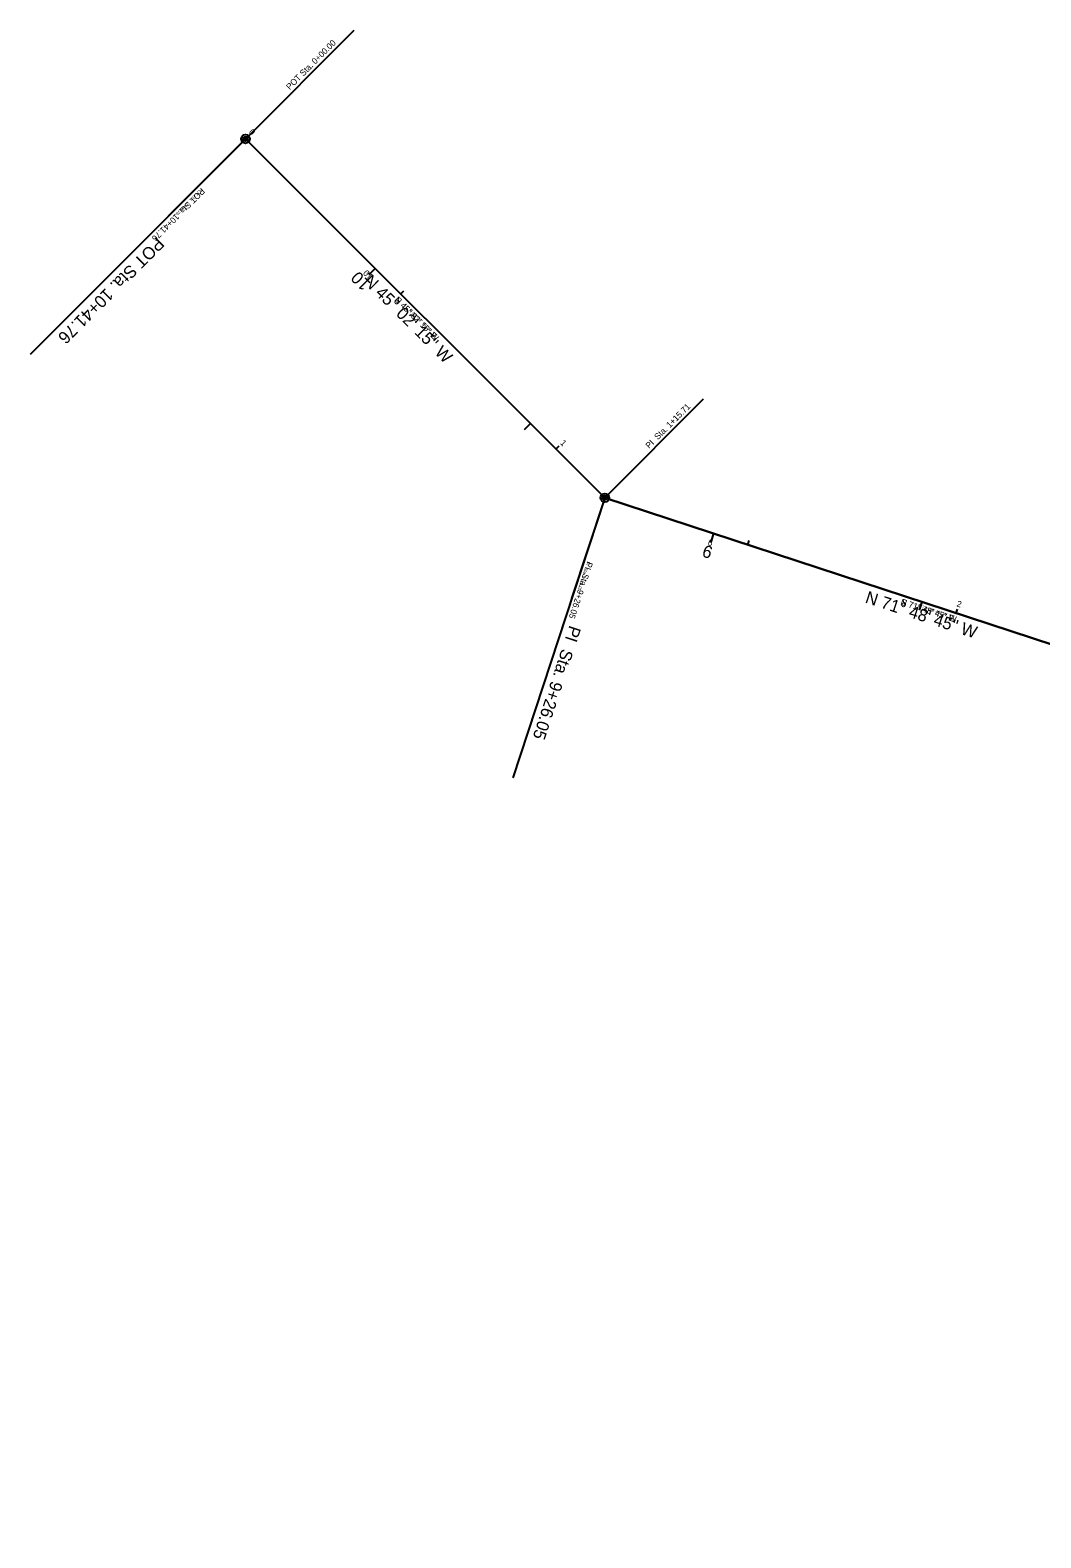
# Model space of a CAD drawing. Extents: x 2261207 to 2264340, y 653057 to 655601.
# Drawn here: x 2261207 to 2261437.3, y 655257 to 655600.6 of the extents above; entities that cross this region are included whole.
import ezdxf

# ---------------------------------------------------------------- set-up
doc = ezdxf.new("R2010")
doc.units = 0
for name, color, linetype in [('CL_X_Construction', 7, 'Continuous'), ('Default', 7, 'Continuous'), ('GE_X_CL_10', 7, 'Continuous'), ('GE_X_CL_20', 7, 'Continuous'), ('GE_X_CL_5', 7, 'Continuous'), ('SC_Scratch1', 7, 'Continuous'), ('SC_Scratch10', 7, 'Continuous'), ('SC_Scratch2', 7, 'Continuous')]:
    doc.layers.add(name, color=color, linetype=linetype)

msp = doc.modelspace()

# ---------------------------------------------------------------- linework, layer by layer
at = {"layer": 'CL_X_Construction'}
for p, q in [((2261337.92, 655494.06), (2261256.04, 655575.83)), ((2261337.92, 655494.06), (2261256.04, 655575.83)), ((2261488.74, 655444.51), (2261337.92, 655494.06)), ((2261488.74, 655444.51), (2261337.92, 655494.06))]:
    msp.add_line(p, q, dxfattribs=at)
at = {"layer": 'Default'}
msp.add_lwpolyline([(2261600.73, 655257.02), (2261565.65, 655295.67), (2261541.65, 655370.74), (2261528.34, 655411.79), (2261488.74, 655444.51), (2261337.92, 655494.06), (2261256.04, 655575.83), (2261256.04, 655575.83)], dxfattribs=at)
at = {"layer": 'GE_X_CL_10'}
for p, q in [((2261255.69, 655575.48), (2261231.52, 655551.27)), ((2261337.92, 655494.06), (2261256.04, 655575.83)), ((2261285.6, 655546.32), (2261284.89, 655545.61)), ((2261320.97, 655510.99), (2261320.27, 655510.28)), ((2261337.76, 655493.59), (2261327.44, 655462.16)), ((2261488.74, 655444.51), (2261337.92, 655494.06)), ((2261362.67, 655485.93), (2261362.36, 655484.98)), ((2261410.17, 655470.32), (2261409.86, 655469.37))]:
    msp.add_line(p, q, dxfattribs=at)
for centre in [(2261256.04, 655575.83), (2261337.92, 655494.06)]:
    msp.add_circle(centre, 0.5, dxfattribs=at)
at = {"layer": 'GE_X_CL_20'}
for p, q in [((2261255.34, 655575.12), (2261206.99, 655526.71)), ((2261255.34, 655575.12), (2261206.99, 655526.71)), ((2261255.34, 655575.12), (2261206.99, 655526.71)), ((2261255.34, 655575.12), (2261206.99, 655526.71)), ((2261337.92, 655494.06), (2261256.04, 655575.83)), ((2261337.92, 655494.06), (2261256.04, 655575.83)), ((2261285.6, 655546.32), (2261284.18, 655544.9)), ((2261285.6, 655546.32), (2261284.18, 655544.9)), ((2261285.6, 655546.32), (2261284.18, 655544.9)), ((2261285.6, 655546.32), (2261284.18, 655544.9)), ((2261320.97, 655510.99), (2261319.56, 655509.57)), ((2261320.97, 655510.99), (2261319.56, 655509.57)), ((2261320.97, 655510.99), (2261319.56, 655509.57)), ((2261320.97, 655510.99), (2261319.56, 655509.57)), ((2261337.61, 655493.11), (2261316.96, 655430.26)), ((2261337.61, 655493.11), (2261316.96, 655430.26)), ((2261337.61, 655493.11), (2261316.96, 655430.26)), ((2261337.61, 655493.11), (2261316.96, 655430.26)), ((2261488.74, 655444.51), (2261337.92, 655494.06)), ((2261488.74, 655444.51), (2261337.92, 655494.06)), ((2261362.67, 655485.93), (2261362.04, 655484.03)), ((2261362.67, 655485.93), (2261362.04, 655484.03)), ((2261362.67, 655485.93), (2261362.04, 655484.03)), ((2261362.67, 655485.93), (2261362.04, 655484.03)), ((2261410.17, 655470.32), (2261409.55, 655468.42)), ((2261410.17, 655470.32), (2261409.55, 655468.42)), ((2261410.17, 655470.32), (2261409.55, 655468.42)), ((2261410.17, 655470.32), (2261409.55, 655468.42))]:
    msp.add_line(p, q, dxfattribs=at)
for centre in [(2261256.04, 655575.83), (2261256.04, 655575.83), (2261256.04, 655575.83), (2261256.04, 655575.83), (2261337.92, 655494.06), (2261337.92, 655494.06), (2261337.92, 655494.06), (2261337.92, 655494.06)]:
    msp.add_circle(centre, 1, dxfattribs=at)
at = {"layer": 'GE_X_CL_5'}
for p, q in [((2261255.69, 655575.48), (2261238.46, 655558.23)), ((2261337.92, 655494.06), (2261256.04, 655575.83)), ((2261285.6, 655546.32), (2261284.89, 655545.61)), ((2261320.97, 655510.99), (2261320.27, 655510.28)), ((2261337.76, 655493.59), (2261330.36, 655471.07)), ((2261488.74, 655444.51), (2261337.92, 655494.06)), ((2261362.67, 655485.93), (2261362.36, 655484.98)), ((2261410.17, 655470.32), (2261409.86, 655469.37))]:
    msp.add_line(p, q, dxfattribs=at)
for centre in [(2261256.04, 655575.83), (2261337.92, 655494.06)]:
    msp.add_circle(centre, 0.25, dxfattribs=at)
at = {"layer": 'SC_Scratch1'}
for p, q in [((2261256.04, 655575.83), (2261337.92, 655494.06)), ((2261337.92, 655494.06), (2261488.74, 655444.51))]:
    msp.add_line(p, q, dxfattribs=at)
at = {"layer": 'SC_Scratch10'}
for p, q in [((2261256.04, 655575.83), (2261337.92, 655494.06)), ((2261337.92, 655494.06), (2261488.74, 655444.51))]:
    msp.add_line(p, q, dxfattribs=at)
at = {"layer": 'SC_Scratch2'}
for p, q in [((2261256.4, 655576.18), (2261280.81, 655600.63)), ((2261256.4, 655576.18), (2261280.81, 655600.63)), ((2261256.04, 655575.83), (2261256.75, 655576.54)), ((2261256.04, 655575.83), (2261256.75, 655576.54)), ((2261256.04, 655575.83), (2261337.92, 655494.06)), ((2261291.42, 655540.5), (2261292.13, 655541.21)), ((2261291.42, 655540.5), (2261292.13, 655541.21)), ((2261338.27, 655494.42), (2261360.4, 655516.57)), ((2261338.27, 655494.42), (2261360.4, 655516.57)), ((2261326.8, 655505.17), (2261327.51, 655505.87)), ((2261326.8, 655505.17), (2261327.51, 655505.87)), ((2261337.92, 655494.06), (2261488.74, 655444.51)), ((2261370.49, 655483.36), (2261370.8, 655484.31)), ((2261370.49, 655483.36), (2261370.8, 655484.31)), ((2261417.99, 655467.75), (2261418.31, 655468.7)), ((2261417.99, 655467.75), (2261418.31, 655468.7))]:
    msp.add_line(p, q, dxfattribs=at)
for centre in [(2261256.04, 655575.83), (2261256.04, 655575.83), (2261337.92, 655494.06), (2261337.92, 655494.06)]:
    msp.add_circle(centre, 0.5, dxfattribs=at)

# ---------------------------------------------------------------- texts
at = {"layer": 'GE_X_CL_10'}
for s, rotation, p in [('POT Sta. 10+41.76', 225.0375, (2261245.94, 655564.72)), ('10', 135.0375, (2261285.16, 655544.63)), ('N 45%%d 02\' 15" W', 315.0375, (2261289.89, 655539.06)), ('9', 161.8126, (2261362.7, 655484.34)), ('PI  Sta. 9+26.05', 251.8126, (2261333.9, 655479.59)), ('N 71%%d 48\' 45" W', 341.8126, (2261405.2, 655469.75))]:
    msp.add_text(s, height=1.4, rotation=rotation, dxfattribs=at).set_placement(p)
at = {"layer": 'GE_X_CL_20'}
for s, rotation, p in [('POT Sta. 10+41.76', 225.0375, (2261235.84, 655553.61)), ('POT Sta. 10+41.76', 225.0375, (2261235.84, 655553.61)), ('POT Sta. 10+41.76', 225.0375, (2261235.84, 655553.61)), ('POT Sta. 10+41.76', 225.0375, (2261235.84, 655553.61)), ('10', 135.0375, (2261284.73, 655542.94)), ('10', 135.0375, (2261284.73, 655542.94)), ('10', 135.0375, (2261284.73, 655542.94)), ('10', 135.0375, (2261284.73, 655542.94)), ('N 45%%d 02\' 15" W', 315.0375, (2261282.79, 655543.18)), ('N 45%%d 02\' 15" W', 315.0375, (2261282.79, 655543.18)), ('9', 161.8126, (2261362.74, 655482.75)), ('9', 161.8126, (2261362.74, 655482.75)), ('9', 161.8126, (2261362.74, 655482.75)), ('9', 161.8126, (2261362.74, 655482.75)), ('N 71%%d 48\' 45" W', 341.8126, (2261397.06, 655470.21)), ('N 71%%d 48\' 45" W', 341.8126, (2261397.06, 655470.21)), ('PI  Sta. 9+26.05', 251.8126, (2261329.88, 655465.12)), ('PI  Sta. 9+26.05', 251.8126, (2261329.88, 655465.12)), ('PI  Sta. 9+26.05', 251.8126, (2261329.88, 655465.12)), ('PI  Sta. 9+26.05', 251.8126, (2261329.88, 655465.12))]:
    msp.add_text(s, height=2.8, rotation=rotation, dxfattribs=at).set_placement(p)
at = {"layer": 'GE_X_CL_5'}
for s, rotation, p in [('POT Sta. 10+41.76', 225.0375, (2261245.94, 655564.72)), ('10', 135.0375, (2261284.82, 655544.97)), ('N 45%%d 02\' 15" W', 315.0375, (2261293.22, 655536.72)), ('9', 161.8126, (2261362.43, 655484.43)), ('PI  Sta. 9+26.05', 251.8126, (2261333.9, 655479.59)), ('N 71%%d 48\' 45" W', 341.8126, (2261409.2, 655469.17))]:
    msp.add_text(s, height=0.7, rotation=rotation, dxfattribs=at).set_placement(p)
at = {"layer": 'SC_Scratch2'}
for s, rotation, p in [('POT Sta. 0+00.00', 45.0375, (2261266.15, 655586.94)), ('POT Sta. 0+00.00', 45.0375, (2261266.15, 655586.94)), ('0', 315.0375, (2261256.71, 655577.29)), ('0', 315.0375, (2261256.71, 655577.29)), ('S 45%%d 02\' 15" E', 315.0375, (2261289.98, 655538.98)), ('PI  Sta. 1+15.71', 45.0375, (2261348.02, 655505.17)), ('PI  Sta. 1+15.71', 45.0375, (2261348.02, 655505.17)), ('1', 315.0375, (2261327.65, 655506.43)), ('1', 315.0375, (2261327.65, 655506.43)), ('S 71%%d 48\' 45" E', 341.8126, (2261405.32, 655469.71)), ('2', 341.8126, (2261417.97, 655469.34)), ('2', 341.8126, (2261417.97, 655469.34))]:
    msp.add_text(s, height=1.4, rotation=rotation, dxfattribs=at).set_placement(p)

doc.saveas('drawing.dxf')
